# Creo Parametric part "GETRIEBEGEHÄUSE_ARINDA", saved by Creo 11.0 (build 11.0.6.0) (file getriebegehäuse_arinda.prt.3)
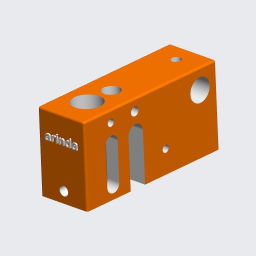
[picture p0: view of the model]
Materials in the file: STAHL

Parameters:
  SCHRAUBEN_GROESSE = "M4x.7"
  METRISCH = "JA"
  WERKSTOFF = "Stahl"
  ERSTELLER = "ARINDA"
  BENENNUNG = "XXX"
  TEILETYP = "K"
  PTC_MASTER_MATERIAL = "STAHL"

Other parameters: STEIGUNG, BOHR_DURCHM, GEWINDEDURCHMESSER, GEWINDEGÄNGE_PRO_INCH, GEWINDETIEFE, GEWINDELÄNGE, MASSE, ANSENKDURCHMESSER, ANSENKTIEFE, KEGELSENKER_DURCHMESSER, SENKWINKEL

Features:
  1. coordinate system
  2. datum plane "RECHTS_Y-Z"
  3. datum plane "OBEN_X-Z"
  4. datum plane "VORNE_X-Y"
  5. datum axis
  6. datum axis
  7. datum axis
  8. datum point "PNT0"
  9. protrusion
  10. hole
  11. hole
  12. hole
  13. hole
  14. hole
  15. hole
  16. hole
  17. cut
  18. hole
  19. cut
  20. cut
  21. hole
  22. round "Rundung 1"
  23. extrusion "Profil 1"

Other named items: GRUNDKÖRPER, STÄNDERBOHRUNG, FIXIERUNG_STÄNDER, UMLENKROLLE, FIXIERUNG_UMLENKROLLE, SPINDEL, FIXIERUNG_SPINDELLAGER, FÜHRUNG_RIEMENSCHEIBE, FENSTER_SPINDEL, FEDERBOHRUNG, FEDERFENSTER, FEDERAUFHÄNGUNG, HEBELBOHRUNG, A_X, A_Y, A_Z, CS0

Layers: 01_ACHSEN, 01_ACHSEN_STD, 01_EBENEN_STD, 01_KOORDSYS_STD, 01_PUNKTE_STD, GEWINDE, SAMMELFLÄCHEN, VOLUMENGEOMETRIE

Notes: M4x.7 | GEWINDEBOHREN | 7.920 |  BOHREN (  | 3.300 | DURCH |   -(  |  ) BOHRUNG | M3x.5 | GEWINDEBOHREN | 6.000 |  BOHREN (  | 2.500 | DURCH |   -(  |  ) BOHRUNG | M3x.5 | GEWINDEBOHREN | DURCH |  BOHREN (  | 2.500 | DURCH |   -(  |  ) BOHRUNG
